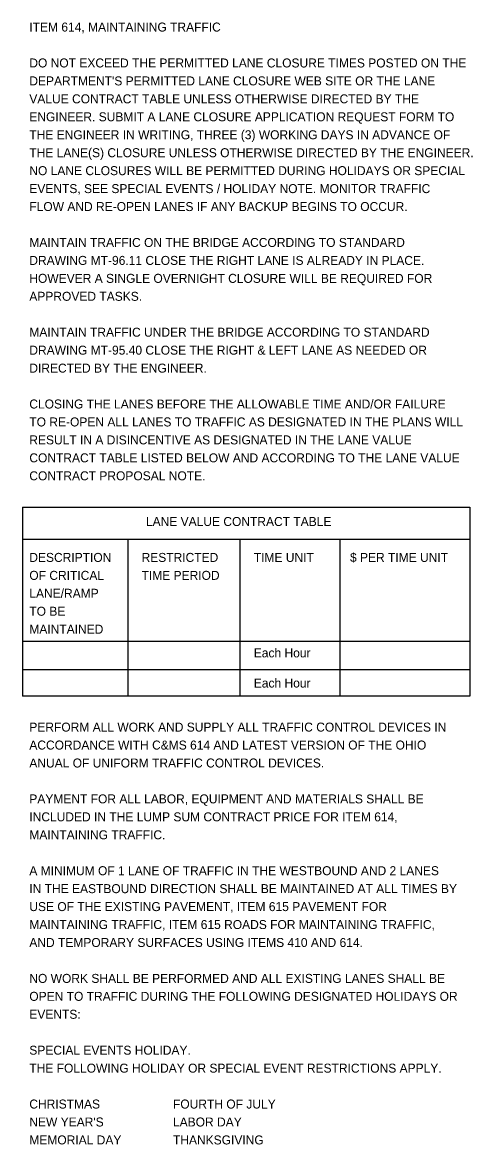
# Model space of a CAD drawing. Extents: x -36 to 68, y -39 to 86.
# Drawn here: x 2.29 to 9.31, y 27.64 to 45.14 of the extents above; entities that cross this region are included whole.
import ezdxf

# ---------------------------------------------------------------- set-up
doc = ezdxf.new("R2010")
doc.units = 0
doc.layers.add('SH_Text', color=7, linetype='Continuous')
doc.layers.add('ST_Text', color=7, linetype='Continuous')

msp = doc.modelspace()

# ---------------------------------------------------------------- linework, layer by layer
at = {"layer": 'ST_Text'}
for p, q in [((2.293, 37.58), (9.27, 37.58)), ((2.293, 37.58), (2.293, 34.635)), ((9.27, 37.58), (9.27, 34.635)), ((2.293, 37.08), (9.27, 37.08)), ((3.937, 37.08), (3.937, 34.635)), ((5.681, 37.08), (5.681, 34.635)), ((7.24, 37.08), (7.24, 34.635)), ((2.293, 35.493), (9.27, 35.493)), ((2.293, 35.049), (9.27, 35.049)), ((9.27, 34.635), (2.293, 34.635))]:
    msp.add_line(p, q, dxfattribs=at)

# ---------------------------------------------------------------- texts
at = {"layer": 'SH_Text'}
for s, p in [('ITEM 614, MAINTAINING TRAFFIC', (2.4, 45)), ('DO NOT EXCEED THE PERMITTED LANE CLOSURE TIMES POSTED ON THE ', (2.4, 44.44)), ("DEPARTMENT'S PERMITTED LANE CLOSURE WEB SITE OR THE LANE ", (2.4, 44.16)), ('VALUE CONTRACT TABLE UNLESS OTHERWISE DIRECTED BY THE ', (2.4, 43.88)), ('ENGINEER. SUBMIT A LANE CLOSURE APPLICATION REQUEST FORM TO ', (2.4, 43.6)), ('THE ENGINEER IN WRITING, THREE (3) WORKING DAYS IN ADVANCE OF ', (2.4, 43.32)), ('THE LANE(S) CLOSURE UNLESS OTHERWISE DIRECTED BY THE ENGINEER. ', (2.4, 43.04)), ('NO LANE CLOSURES WILL BE PERMITTED DURING HOLIDAYS OR SPECIAL ', (2.4, 42.76)), ('EVENTS, SEE SPECIAL EVENTS / HOLIDAY NOTE. MONITOR TRAFFIC ', (2.4, 42.48)), ('FLOW AND RE-OPEN LANES IF ANY BACKUP BEGINS TO OCCUR.', (2.4, 42.2)), ('MAINTAIN TRAFFIC ON THE BRIDGE ACCORDING TO STANDARD ', (2.4, 41.64)), ('DRAWING MT-96.11 CLOSE THE RIGHT LANE IS ALREADY IN PLACE. ', (2.4, 41.36)), ('HOWEVER A SINGLE OVERNIGHT CLOSURE WILL BE REQUIRED FOR ', (2.4, 41.08)), ('APPROVED TASKS.', (2.4, 40.8)), ('MAINTAIN TRAFFIC UNDER THE BRIDGE ACCORDING TO STANDARD ', (2.4, 40.24)), ('DRAWING MT-95.40 CLOSE THE RIGHT & LEFT LANE AS NEEDED OR ', (2.4, 39.96)), ('DIRECTED BY THE ENGINEER.', (2.4, 39.68)), ('CLOSING THE LANES BEFORE THE ALLOWABLE TIME AND/OR FAILURE ', (2.4, 39.12)), ('TO RE-OPEN ALL LANES TO TRAFFIC AS DESIGNATED IN THE PLANS WILL ', (2.4, 38.84)), ('RESULT IN A DISINCENTIVE AS DESIGNATED IN THE LANE VALUE ', (2.4, 38.56)), ('CONTRACT TABLE LISTED BELOW AND ACCORDING TO THE LANE VALUE ', (2.4, 38.28)), ('CONTRACT PROPOSAL NOTE.', (2.4, 38)), ('PERFORM ALL WORK AND SUPPLY ALL TRAFFIC CONTROL DEVICES IN ', (2.4, 34.08)), ('ACCORDANCE WITH C&MS 614 AND LATEST VERSION OF THE OHIO ', (2.4, 33.8)), ('ANUAL OF UNIFORM TRAFFIC CONTROL DEVICES.', (2.4, 33.52)), ('PAYMENT FOR ALL LABOR, EQUIPMENT AND MATERIALS SHALL BE ', (2.4, 32.96)), ('INCLUDED IN THE LUMP SUM CONTRACT PRICE FOR ITEM 614, ', (2.4, 32.68)), ('MAINTAINING TRAFFIC.', (2.4, 32.4)), ('A MINIMUM OF 1 LANE OF TRAFFIC IN THE WESTBOUND AND 2 LANES ', (2.4, 31.84)), ('IN THE EASTBOUND DIRECTION SHALL BE MAINTAINED AT ALL TIMES BY ', (2.4, 31.56)), ('USE OF THE EXISTING PAVEMENT, ITEM 615 PAVEMENT FOR ', (2.4, 31.28)), ('MAINTAINING TRAFFIC, ITEM 615 ROADS FOR MAINTAINING TRAFFIC, ', (2.4, 31)), ('AND TEMPORARY SURFACES USING ITEMS 410 AND 614.', (2.4, 30.72)), ('NO WORK SHALL BE PERFORMED AND ALL EXISTING LANES SHALL BE ', (2.4, 30.16)), ('OPEN TO TRAFFIC DURING THE FOLLOWING DESIGNATED HOLIDAYS OR ', (2.4, 29.88)), ('EVENTS:', (2.4, 29.6)), ('SPECIAL EVENTS HOLIDAY.', (2.4, 29.04)), ('THE FOLLOWING HOLIDAY OR SPECIAL EVENT RESTRICTIONS APPLY.', (2.4, 28.76)), ('CHRISTMAS', (2.4, 28.2)), ('FOURTH OF JULY', (4.64, 28.2)), ("NEW YEAR'S", (2.4, 27.92)), ('LABOR DAY', (4.64, 27.92)), ('MEMORIAL DAY', (2.4, 27.64)), ('THANKSGIVING', (4.64, 27.64))]:
    msp.add_text(s, height=0.14, dxfattribs=at).set_placement(p)
at = {"layer": 'ST_Text'}
for s, p in [('LANE VALUE CONTRACT TABLE', (4.218, 37.287)), ('DESCRIPTION ', (2.4, 36.727)), ('RESTRICTED', (4.15, 36.727)), ('TIME UNIT', (5.9, 36.727)), ('$ PER TIME UNIT', (7.4, 36.727)), ('OF CRITICAL ', (2.4, 36.447)), ('TIME PERIOD', (4.15, 36.447)), ('LANE/RAMP ', (2.4, 36.167)), ('TO BE ', (2.4, 35.887)), ('MAINTAINED', (2.4, 35.607)), ('Each Hour', (5.9, 35.238)), ('Each Hour', (5.9, 34.767))]:
    msp.add_text(s, height=0.14, dxfattribs=at).set_placement(p)

doc.saveas('drawing.dxf')
